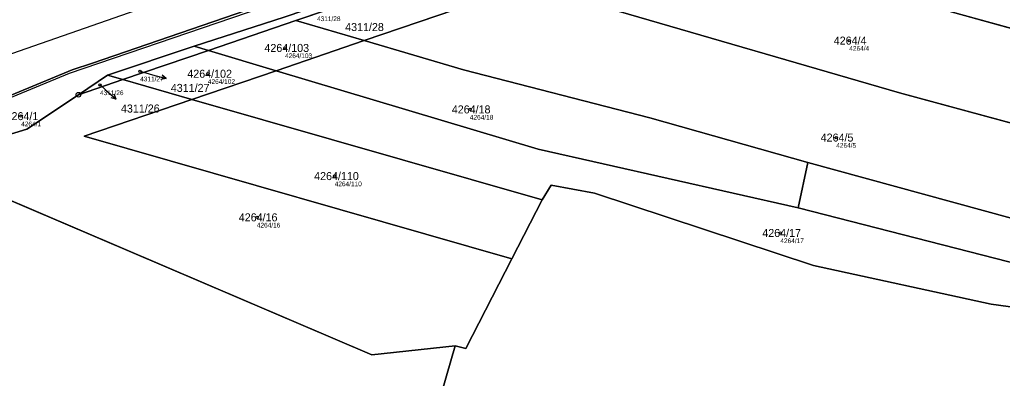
# Model space of a CAD drawing. Extents: x -739214 to -733252, y -1147612 to -1142842.
# Drawn here: x -737116.4 to -736907.7, y -1146195.3 to -1146119.1 of the extents above; entities that cross this region are included whole.
import ezdxf

# ---------------------------------------------------------------- set-up
doc = ezdxf.new("R2010")
doc.units = 0
for name, color, linetype in [('Definiční body', 7, 'Continuous'), ('Hranice parcel', 7, 'Continuous'), ('Parcelní čísla', 7, 'Continuous'), ('Polygon parcely', 7, 'Continuous'), ('Pop  PČ popisy', 7, 'Continuous'), ('Poz předměty', 7, 'Continuous'), ('Vnitřní kresba', 7, 'Continuous'), ('Značky bodu BP', 7, 'Continuous')]:
    doc.layers.add(name, color=color, linetype=linetype)

msp = doc.modelspace()

# ---------------------------------------------------------------- linework, layer by layer
at = {"layer": 'Definiční body'}
for centre in [(-736940.19, -1146123.57), (-737060.06, -1146125.13), (-737090.84, -1146130.07), (-737076.44, -1146130.61), (-737099.36, -1146133), (-737020.79, -1146138.19), (-737116.11, -1146139.62), (-736942.96, -1146144.17), (-737049.5, -1146152.35), (-737066.04, -1146161.12), (-736954.83, -1146164.44)]:
    msp.add_circle(centre, 0.25, dxfattribs=at)
at = {"layer": 'Hranice parcel'}
for p, q in [((-736977.4, -1146101.1), (-736898.55, -1146122.95)), ((-737057.73, -1146119.32), (-737022.29, -1146107.24)), ((-737008.18, -1146111.58), (-737043.27, -1146123.57)), ((-736991.48, -1146116.71), (-736929.53, -1146134.68)), ((-737076.33, -1146125.66), (-737057.73, -1146119.32)), ((-737057.73, -1146119.32), (-737043.27, -1146123.57)), ((-737097.76, -1146130.94), (-737079.35, -1146124.75)), ((-737076.33, -1146125.66), (-737079.35, -1146124.75)), ((-737043.27, -1146123.57), (-737061.97, -1146129.96)), ((-737043.27, -1146123.57), (-737022.12, -1146129.78)), ((-737094.52, -1146131.86), (-737076.33, -1146125.66)), ((-737061.97, -1146129.96), (-737076.33, -1146125.66)), ((-737103.94, -1146135.07), (-737097.76, -1146130.94)), ((-737094.52, -1146131.86), (-737097.76, -1146130.94)), ((-737061.97, -1146129.96), (-737079.85, -1146136.07)), ((-737006.3, -1146146.61), (-737061.97, -1146129.96)), ((-737103.94, -1146135.07), (-737094.52, -1146131.86)), ((-737079.85, -1146136.07), (-737094.52, -1146131.86)), ((-736929.53, -1146134.68), (-736887.15, -1146146.15)), ((-737079.85, -1146136.07), (-737005.4, -1146157.41)), ((-736951.05, -1146159.13), (-737006.3, -1146146.61)), ((-736949, -1146149.47), (-736951.05, -1146159.13)), ((-736949, -1146149.47), (-736868.58, -1146171.48)), ((-737041.63, -1146190.31), (-737129.19, -1146152.93)), ((-737005.4, -1146157.41), (-737011.85, -1146169.96)), ((-736951.05, -1146159.13), (-736889.7, -1146174.8)), ((-737011.85, -1146169.96), (-737021.63, -1146188.99)), ((-737023.93, -1146188.41), (-737041.63, -1146190.31)), ((-737023.93, -1146188.41), (-737031.55, -1146214.89)), ((-737021.63, -1146188.99), (-737023.93, -1146188.41))]:
    msp.add_line(p, q, dxfattribs=at)
for points in [[(-736968.59, -1146082.9), (-736970.23, -1146083.43), (-737100.95, -1146128.37), (-737105.29, -1146129.81), (-737124.99, -1146137.9)], [(-737079.35, -1146124.75), (-737060.25, -1146118.58), (-737024.71, -1146106.5)], [(-737022.12, -1146129.78), (-736982.56, -1146139.99), (-736949, -1146149.47)], [(-737129.54, -1146146.83), (-737114.93, -1146142.42), (-737103.94, -1146135.07)], [(-737011.85, -1146169.96), (-737102.76, -1146143.89), (-737079.85, -1146136.07)], [(-736881.65, -1146183.43), (-736910.07, -1146179.55), (-736947.77, -1146171.35), (-736994.32, -1146155.97), (-737003.53, -1146154.25), (-737005.4, -1146157.41)]]:
    msp.add_lwpolyline(points, dxfattribs=at)
at = {"layer": 'Polygon parcely'}
msp.add_lwpolyline([(-737124.99, -1146137.9), (-737105.29, -1146129.81), (-737100.95, -1146128.37), (-736970.23, -1146083.43), (-736968.59, -1146082.9), (-736945.99, -1146075.63), (-736905.56, -1146062.63), (-736903.36, -1146061.92), (-736885.68, -1146056.23), (-736865.38, -1146049.7), (-736840.67, -1146041), (-736817.62, -1146032.76), (-736814.98, -1146031.96), (-736778.13, -1146019.56), (-736763.95, -1146014.79), (-736730.03, -1146025.05), (-736717.9, -1145969.83)], dxfattribs=at)
for points in [[(-737079.35, -1146124.75), (-737060.25, -1146118.58), (-737024.71, -1146106.5), (-736995.26, -1146096.15), (-736963.07, -1146084.94), (-736968.59, -1146082.9), (-736970.23, -1146083.43), (-737100.95, -1146128.37), (-737105.29, -1146129.81), (-737124.99, -1146137.9), (-737126.51, -1146140.92), (-737129.54, -1146146.83), (-737114.93, -1146142.42), (-737103.94, -1146135.07), (-737097.76, -1146130.94)], [(-736963.3, -1146099.04), (-736972.94, -1146102.24), (-736973.73, -1146099.86), (-736977.4, -1146101.1), (-736898.55, -1146122.95), (-736903.07, -1146112.75), (-736903.81, -1146110.98), (-736904.64, -1146109.25), (-736905.56, -1146107.57), (-736905.95, -1146106.9), (-736906.99, -1146105.29), (-736908.12, -1146103.74), (-736909.32, -1146102.24), (-736910.6, -1146100.81), (-736911.95, -1146099.45), (-736923.65, -1146096.16), (-736944.18, -1146090.32), (-736948.02, -1146091.35), (-736964.08, -1146096.67)], [(-736983.7, -1146103.21), (-737008.18, -1146111.58), (-736991.48, -1146116.71), (-736929.53, -1146134.68), (-736887.15, -1146146.15), (-736888.82, -1146143.39), (-736889.7, -1146141.83), (-736891.24, -1146138.99), (-736892.68, -1146136.1), (-736894.03, -1146133.17), (-736898.55, -1146122.95), (-736977.4, -1146101.1)], [(-737057.73, -1146119.32), (-737022.29, -1146107.24), (-737024.71, -1146106.5), (-737060.25, -1146118.58), (-737079.35, -1146124.75), (-737076.33, -1146125.66)], [(-737043.27, -1146123.57), (-737008.18, -1146111.58), (-737022.29, -1146107.24), (-737057.73, -1146119.32)], [(-736949, -1146149.47), (-736868.58, -1146171.48), (-736862.84, -1146173.19), (-736865.37, -1146171.14), (-736867.83, -1146169.02), (-736870.22, -1146166.82), (-736872.55, -1146164.55), (-736874.8, -1146162.21), (-736875.34, -1146161.64), (-736877.5, -1146159.21), (-736879.59, -1146156.72), (-736881.6, -1146154.17), (-736883.53, -1146151.55), (-736885.38, -1146148.88), (-736887.15, -1146146.15), (-736929.53, -1146134.68), (-736991.48, -1146116.71), (-737008.18, -1146111.58), (-737043.27, -1146123.57), (-737022.12, -1146129.78), (-736982.56, -1146139.99)], [(-737057.73, -1146119.32), (-737076.33, -1146125.66), (-737061.97, -1146129.96), (-737043.27, -1146123.57)], [(-737094.52, -1146131.86), (-737076.33, -1146125.66), (-737079.35, -1146124.75), (-737097.76, -1146130.94)], [(-737043.27, -1146123.57), (-737061.97, -1146129.96), (-737006.3, -1146146.61), (-736951.05, -1146159.13), (-736949, -1146149.47), (-736982.56, -1146139.99), (-737022.12, -1146129.78)], [(-737061.97, -1146129.96), (-737076.33, -1146125.66), (-737094.52, -1146131.86), (-737079.85, -1146136.07)], [(-737094.52, -1146131.86), (-737097.76, -1146130.94), (-737103.94, -1146135.07)], [(-737005.4, -1146157.41), (-737003.53, -1146154.25), (-736994.32, -1146155.97), (-736947.77, -1146171.35), (-736910.07, -1146179.55), (-736881.65, -1146183.43), (-736883.52, -1146180.99), (-736889.7, -1146174.8), (-736951.05, -1146159.13), (-737006.3, -1146146.61), (-737061.97, -1146129.96), (-737079.85, -1146136.07)], [(-737129.19, -1146152.93), (-737041.63, -1146190.31), (-737023.93, -1146188.41), (-737021.63, -1146188.99), (-737011.85, -1146169.96), (-737102.76, -1146143.89), (-737079.85, -1146136.07), (-737094.52, -1146131.86), (-737103.94, -1146135.07), (-737114.93, -1146142.42), (-737129.54, -1146146.83), (-737132.04, -1146151.71)], [(-737011.85, -1146169.96), (-737005.4, -1146157.41), (-737079.85, -1146136.07), (-737102.76, -1146143.89)], [(-736830.31, -1146190.25), (-736833.39, -1146189.22), (-736836.44, -1146188.09), (-736839.45, -1146186.87), (-736842.43, -1146185.55), (-736845.36, -1146184.15), (-736846.39, -1146183.62), (-736849.26, -1146182.1), (-736852.09, -1146180.49), (-736854.86, -1146178.79), (-736857.58, -1146177), (-736860.24, -1146175.14), (-736862.84, -1146173.19), (-736868.58, -1146171.48), (-736949, -1146149.47), (-736951.05, -1146159.13), (-736889.7, -1146174.8), (-736865.53, -1146181.85), (-736831.06, -1146194.05)], [(-737129.19, -1146152.93), (-737133.4, -1146154.36), (-737136.7, -1146160.81), (-737147.08, -1146179.95), (-737157.67, -1146197.66), (-737165.43, -1146207.35), (-737142.57, -1146223.75), (-737137.82, -1146224.62), (-737096.8, -1146233.26), (-737094.21, -1146234.22), (-737083.85, -1146218.83), (-737072.78, -1146210.05), (-737065.15, -1146207.75), (-737040.26, -1146217.67), (-737037.39, -1146213.21), (-737031.55, -1146214.89), (-737023.93, -1146188.41), (-737041.63, -1146190.31)], [(-737021.63, -1146188.99), (-737023.93, -1146188.41), (-737031.55, -1146214.89), (-736983.7, -1146228.83), (-736939.24, -1146237.89), (-736893.84, -1146248.24), (-736833.12, -1146266.08), (-736826.14, -1146238.17), (-736825.87, -1146235.87), (-736828.32, -1146235.2), (-736868.17, -1146224.99), (-736872.34, -1146205.13), (-736874.93, -1146196.5), (-736878.24, -1146189.59), (-736881.65, -1146183.43), (-736910.07, -1146179.55), (-736947.77, -1146171.35), (-736994.32, -1146155.97), (-737003.53, -1146154.25), (-737005.4, -1146157.41), (-737011.85, -1146169.96)]]:
    msp.add_lwpolyline(points, close=True, dxfattribs=at)
at = {"layer": 'Pop  PČ popisy'}
for p, q in [((-737090.84, -1146130.07), (-737088.21, -1146130.82)), ((-737088.21, -1146130.82), (-737085.33, -1146131.65)), ((-737085.33, -1146131.65), (-737086.43, -1146131.85)), ((-737085.33, -1146131.65), (-737086.15, -1146130.89)), ((-737099.36, -1146133), (-737098.17, -1146134.04)), ((-737098.17, -1146134.04), (-737095.91, -1146136.01)), ((-737095.91, -1146136.01), (-737096.99, -1146135.73)), ((-737095.91, -1146136.01), (-737096.33, -1146134.97))]:
    msp.add_line(p, q, dxfattribs=at)
at = {"layer": 'Poz předměty'}
msp.add_line((-738196.39, -1146502.42), (-736812.26, -1146019.61), dxfattribs=at)
at = {"layer": 'Vnitřní kresba'}
for p, q in [((-736970.07, -1146083.9), (-737105.88, -1146130.59)), ((-737105.88, -1146130.59), (-737124.8, -1146138.36))]:
    msp.add_line(p, q, dxfattribs=at)
at = {"layer": 'Značky bodu BP'}
for radius in [0.5, 0.0303]:
    msp.add_circle((-737103.94, -1146135.07), radius, dxfattribs=at)

# ---------------------------------------------------------------- texts
at = {"layer": 'Definiční body'}
for s, p in [('4311/28', (-737053.26, -1146119.43)), ('4264/4', (-736940.19, -1146125.73)), ('4264/103', (-737060.06, -1146127.29)), ('4311/27', (-737090.84, -1146132.23)), ('4264/102', (-737076.44, -1146132.77)), ('4311/26', (-737099.36, -1146135.16)), ('4264/18', (-737020.79, -1146140.35)), ('4264/1', (-737116.11, -1146141.78)), ('4264/5', (-736942.96, -1146146.33)), ('4264/110', (-737049.5, -1146154.51)), ('4264/16', (-737066.04, -1146163.28)), ('4264/17', (-736954.83, -1146166.6))]:
    msp.add_text(s, height=1, dxfattribs=at).set_placement(p)
at = {"layer": 'Parcelní čísla'}
for s, p in [('4311/28', (-737047.28, -1146121.54)), ('4264/4', (-736943.49, -1146124.42)), ('4264/103', (-737064.43, -1146125.98)), ('4264/102', (-737080.81, -1146131.46)), ('4311/27', (-737084.32, -1146134.47)), ('4311/26', (-737094.91, -1146138.85)), ('4264/18', (-737024.63, -1146139.04)), ('4264/1', (-737119.42, -1146140.47)), ('4264/5', (-736946.27, -1146145.02)), ('4264/110', (-737053.87, -1146153.2)), ('4264/16', (-737069.88, -1146161.97)), ('4264/17', (-736958.67, -1146165.29))]:
    msp.add_text(s, height=1.7, dxfattribs=at).set_placement(p)

doc.saveas('drawing.dxf')
